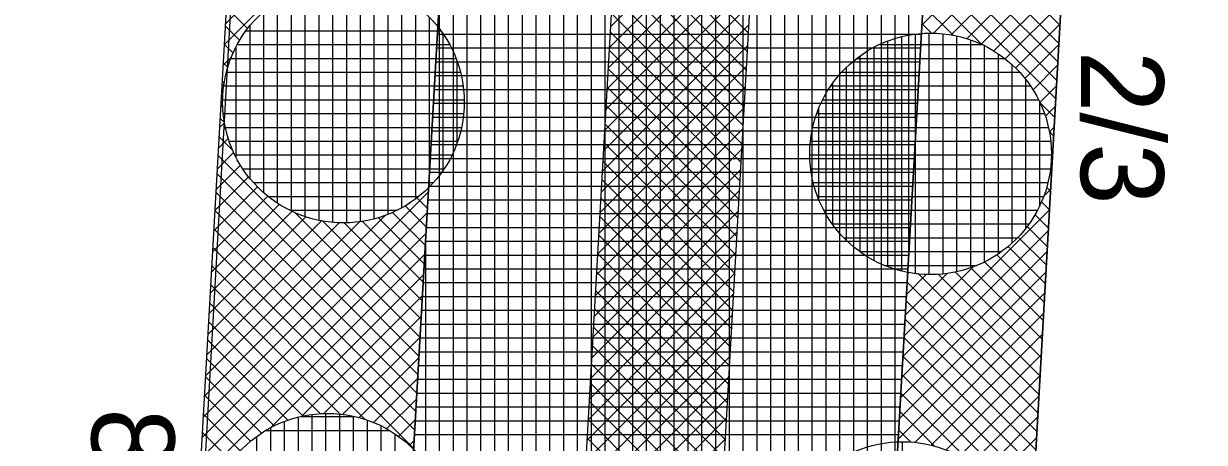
# Model space of a CAD drawing. Extents: x -565346 to -564154, y -1097386 to -1095620.
# Drawn here: x -564301.42 to -564284.31, y -1097175.5 to -1097169.44 of the extents above; entities that cross this region are included whole.
import ezdxf

# ---------------------------------------------------------------- set-up
doc = ezdxf.new("R2010")
doc.units = 0
for name, color, linetype in [('Vrstva 1', 7, 'Continuous'), ('Vrstva 13', 7, 'Continuous'), ('Vrstva 40', 7, 'Continuous'), ('Vrstva 41', 7, 'Continuous'), ('Vrstva 42', 7, 'Continuous'), ('Vrstva 43', 7, 'Continuous'), ('Vrstva 44', 7, 'Continuous')]:
    doc.layers.add(name, color=color, linetype=linetype)

msp = doc.modelspace()

# ---------------------------------------------------------------- linework, layer by layer
at = {"layer": 'Vrstva 1'}
msp.add_line((-564307.09, -1097322.09), (-564296.5, -1097135.53), dxfattribs=at)
at = {"layer": 'Vrstva 13'}
msp.add_line((-564284.61, -1097137.94), (-564287.03, -1097180.53), dxfattribs=at)
at = {"layer": 'Vrstva 41'}
for points in [[(-564307.383, -1097332.191), (-564304.399, -1097332.838), (-564304.096, -1097322.37), (-564303.226, -1097307.04), (-564296.016, -1097180.02), (-564294.347, -1097150.646), (-564297.42, -1097150.37), (-564307.09, -1097322.09)], [(-564297.082, -1097322.329), (-564302.848, -1097333.175), (-564300.817, -1097333.615), (-564295.11, -1097322.88), (-564285.364, -1097151.156), (-564287.358, -1097151.043), (-564289.027, -1097180.417), (-564293.197, -1097253.877), (-564296.237, -1097307.437)]]:
    msp.add_lwpolyline(points, close=True, dxfattribs=at)
at = {"layer": 'Vrstva 42'}
for p, q in [((-564295.23, -1097166.181), (-564298.494, -1097169.446)), ((-564295.247, -1097166.481), (-564298.511, -1097169.745)), ((-564290.789, -1097167.357), (-564292.913, -1097169.481)), ((-564286.283, -1097167.34), (-564288.405, -1097169.461)), ((-564288.297, -1097167.563), (-564286.403, -1097169.457)), ((-564290.806, -1097167.656), (-564292.93, -1097169.781)), ((-564292.811, -1097167.681), (-564290.915, -1097169.577)), ((-564286.3, -1097167.64), (-564288.236, -1097169.576)), ((-564290.823, -1097167.956), (-564292.947, -1097170.08)), ((-564292.826, -1097167.949), (-564290.93, -1097169.845)), ((-564288.312, -1097167.831), (-564286.418, -1097169.725)), ((-564286.317, -1097167.939), (-564287.979, -1097169.601)), ((-564288.327, -1097168.099), (-564286.433, -1097169.992)), ((-564290.84, -1097168.256), (-564292.964, -1097170.38)), ((-564292.841, -1097168.217), (-564290.946, -1097170.112)), ((-564286.334, -1097168.239), (-564287.75, -1097169.655)), ((-564288.342, -1097168.366), (-564286.449, -1097170.26)), ((-564290.857, -1097168.556), (-564292.981, -1097170.68)), ((-564292.856, -1097168.484), (-564290.961, -1097170.38)), ((-564288.357, -1097168.634), (-564286.464, -1097170.528)), ((-564286.351, -1097168.539), (-564287.545, -1097169.733)), ((-564292.872, -1097168.752), (-564290.976, -1097170.648)), ((-564290.874, -1097168.856), (-564292.998, -1097170.98)), ((-564288.373, -1097168.902), (-564287.536, -1097169.738)), ((-564286.368, -1097168.839), (-564287.361, -1097169.832)), ((-564290.891, -1097169.156), (-564293.015, -1097171.28)), ((-564292.887, -1097169.02), (-564290.991, -1097170.915)), ((-564286.385, -1097169.139), (-564287.195, -1097169.949)), ((-564298.48, -1097169.199), (-564298.171, -1097169.509)), ((-564292.902, -1097169.287), (-564291.006, -1097171.183)), ((-564288.388, -1097169.169), (-564287.952, -1097169.606)), ((-564298.495, -1097169.467), (-564298.286, -1097169.677)), ((-564295.417, -1097169.48), (-564295.419, -1097169.482)), ((-564290.908, -1097169.456), (-564293.032, -1097171.58)), ((-564288.403, -1097169.437), (-564288.265, -1097169.574)), ((-564286.402, -1097169.439), (-564287.045, -1097170.082)), ((-564292.917, -1097169.555), (-564291.022, -1097171.451)), ((-564298.51, -1097169.735), (-564298.383, -1097169.862)), ((-564290.925, -1097169.756), (-564293.049, -1097171.88)), ((-564292.933, -1097169.822), (-564291.037, -1097171.718)), ((-564286.419, -1097169.739), (-564286.911, -1097170.23)), ((-564298.406, -1097169.924), (-564298.528, -1097170.045)), ((-564298.526, -1097170.003), (-564298.458, -1097170.07)), ((-564290.942, -1097170.055), (-564293.066, -1097172.18)), ((-564292.948, -1097170.09), (-564291.052, -1097171.986)), ((-564286.436, -1097170.038), (-564286.793, -1097170.395)), ((-564298.512, -1097170.312), (-564298.545, -1097170.345)), ((-564298.541, -1097170.27), (-564298.51, -1097170.301)), ((-564290.959, -1097170.355), (-564293.083, -1097172.479)), ((-564286.453, -1097170.338), (-564286.692, -1097170.578)), ((-564292.963, -1097170.358), (-564291.067, -1097172.253)), ((-564298.532, -1097170.615), (-564298.562, -1097170.645)), ((-564298.556, -1097170.538), (-564298.533, -1097170.561)), ((-564290.976, -1097170.655), (-564293.101, -1097172.779)), ((-564292.978, -1097170.625), (-564291.082, -1097172.521)), ((-564286.688, -1097170.586), (-564286.479, -1097170.795)), ((-564286.47, -1097170.638), (-564286.611, -1097170.779)), ((-564298.571, -1097170.806), (-564298.506, -1097170.87)), ((-564298.506, -1097170.872), (-564298.579, -1097170.944)), ((-564290.993, -1097170.955), (-564293.118, -1097173.079)), ((-564292.993, -1097170.893), (-564291.098, -1097172.789)), ((-564286.556, -1097171.002), (-564286.494, -1097171.063)), ((-564286.487, -1097170.938), (-564286.555, -1097171.006)), ((-564298.452, -1097171.101), (-564298.595, -1097171.244)), ((-564298.586, -1097171.074), (-564298.389, -1097171.271)), ((-564293.009, -1097171.161), (-564291.113, -1097173.056)), ((-564298.373, -1097171.305), (-564298.612, -1097171.544)), ((-564298.601, -1097171.341), (-564295.688, -1097174.254)), ((-564291.01, -1097171.255), (-564293.135, -1097173.379)), ((-564286.504, -1097171.238), (-564286.527, -1097171.261)), ((-564286.524, -1097171.315), (-564286.509, -1097171.331)), ((-564298.274, -1097171.489), (-564298.629, -1097171.843)), ((-564293.024, -1097171.428), (-564291.128, -1097173.324)), ((-564286.521, -1097171.538), (-564286.542, -1097171.559)), ((-564298.158, -1097171.655), (-564298.646, -1097172.143)), ((-564298.616, -1097171.609), (-564295.704, -1097174.522)), ((-564291.028, -1097171.555), (-564293.152, -1097173.679)), ((-564293.039, -1097171.696), (-564291.143, -1097173.592)), ((-564286.545, -1097171.578), (-564286.525, -1097171.598)), ((-564295.553, -1097171.879), (-564298.815, -1097175.14)), ((-564298.025, -1097171.804), (-564298.663, -1097172.443)), ((-564298.631, -1097171.877), (-564295.719, -1097174.789)), ((-564295.568, -1097171.829), (-564295.552, -1097171.845)), ((-564291.045, -1097171.855), (-564293.169, -1097173.979)), ((-564286.538, -1097171.838), (-564286.637, -1097171.937)), ((-564286.595, -1097171.81), (-564286.54, -1097171.866)), ((-564297.711, -1097172.056), (-564298.697, -1097173.042)), ((-564297.876, -1097171.939), (-564298.68, -1097172.743)), ((-564295.719, -1097171.961), (-564295.567, -1097172.113)), ((-564293.054, -1097171.964), (-564291.158, -1097173.859)), ((-564286.669, -1097172.02), (-564286.555, -1097172.134)), ((-564295.57, -1097172.179), (-564298.832, -1097175.44)), ((-564296.166, -1097172.209), (-564298.798, -1097174.841)), ((-564297.528, -1097172.157), (-564298.714, -1097173.342)), ((-564298.646, -1097172.145), (-564295.734, -1097175.057)), ((-564297.481, -1097172.179), (-564295.673, -1097173.986)), ((-564296.072, -1097172.173), (-564295.597, -1097172.648)), ((-564295.887, -1097172.076), (-564295.582, -1097172.381)), ((-564291.062, -1097172.155), (-564293.186, -1097174.279)), ((-564293.069, -1097172.231), (-564291.174, -1097174.127)), ((-564286.555, -1097172.137), (-564288.677, -1097174.259)), ((-564286.764, -1097172.208), (-564286.57, -1097172.401)), ((-564296.546, -1097172.305), (-564298.781, -1097174.541)), ((-564296.841, -1097172.318), (-564298.764, -1097174.241)), ((-564297.097, -1097172.291), (-564298.747, -1097173.942)), ((-564297.326, -1097172.238), (-564298.73, -1097173.642)), ((-564297.084, -1097172.293), (-564295.658, -1097173.719)), ((-564296.771, -1097172.323), (-564295.643, -1097173.451)), ((-564296.511, -1097172.3), (-564295.628, -1097173.183)), ((-564296.28, -1097172.248), (-564295.612, -1097172.916)), ((-564286.877, -1097172.377), (-564286.585, -1097172.669)), ((-564295.588, -1097172.479), (-564298.849, -1097175.74)), ((-564298.661, -1097172.412), (-564295.749, -1097175.325)), ((-564291.079, -1097172.455), (-564293.203, -1097174.579)), ((-564293.085, -1097172.499), (-564291.189, -1097174.395)), ((-564286.572, -1097172.437), (-564288.694, -1097174.559)), ((-564287.008, -1097172.529), (-564286.6, -1097172.937)), ((-564298.676, -1097172.68), (-564295.764, -1097175.592)), ((-564286.589, -1097172.737), (-564288.711, -1097174.859)), ((-564287.154, -1097172.666), (-564286.616, -1097173.204)), ((-564295.605, -1097172.779), (-564298.866, -1097176.04)), ((-564291.096, -1097172.754), (-564293.22, -1097174.879)), ((-564293.1, -1097172.766), (-564291.204, -1097174.662)), ((-564287.496, -1097172.889), (-564286.646, -1097173.739)), ((-564287.316, -1097172.786), (-564286.631, -1097173.472)), ((-564298.691, -1097172.948), (-564296.467, -1097175.172)), ((-564295.622, -1097173.079), (-564297.832, -1097175.289)), ((-564291.113, -1097173.054), (-564293.237, -1097175.178)), ((-564293.115, -1097173.034), (-564291.219, -1097174.93)), ((-564286.606, -1097173.037), (-564288.728, -1097175.159)), ((-564287.661, -1097172.961), (-564288.66, -1097173.96)), ((-564288.039, -1097173.056), (-564288.643, -1097173.66)), ((-564288.334, -1097173.068), (-564288.626, -1097173.36)), ((-564288.59, -1097173.041), (-564288.609, -1097173.06)), ((-564288.463, -1097173.054), (-564286.707, -1097174.81)), ((-564288.166, -1097173.068), (-564286.692, -1097174.542)), ((-564287.915, -1097173.037), (-564286.676, -1097174.275)), ((-564287.695, -1097172.974), (-564286.661, -1097174.007)), ((-564298.707, -1097173.216), (-564296.828, -1097175.094)), ((-564288.616, -1097173.184), (-564286.722, -1097175.078)), ((-564295.639, -1097173.378), (-564297.384, -1097175.124)), ((-564291.13, -1097173.354), (-564293.254, -1097175.478)), ((-564293.13, -1097173.302), (-564291.234, -1097175.197)), ((-564286.623, -1097173.337), (-564288.745, -1097175.459)), ((-564298.722, -1097173.484), (-564297.116, -1097175.09)), ((-564293.145, -1097173.569), (-564291.25, -1097175.465)), ((-564288.631, -1097173.451), (-564286.737, -1097175.345)), ((-564298.737, -1097173.751), (-564297.368, -1097175.12)), ((-564295.656, -1097173.678), (-564297.064, -1097175.087)), ((-564291.147, -1097173.654), (-564293.271, -1097175.778)), ((-564288.646, -1097173.719), (-564286.752, -1097175.613)), ((-564286.64, -1097173.637), (-564288.507, -1097175.504)), ((-564293.161, -1097173.837), (-564291.265, -1097175.733)), ((-564286.657, -1097173.937), (-564288.267, -1097175.546)), ((-564298.752, -1097174.019), (-564297.588, -1097175.183)), ((-564295.673, -1097173.978), (-564296.794, -1097175.1)), ((-564291.164, -1097173.954), (-564293.288, -1097176.078)), ((-564293.176, -1097174.105), (-564291.28, -1097176)), ((-564288.662, -1097173.987), (-564286.768, -1097175.881)), ((-564298.767, -1097174.287), (-564297.787, -1097175.266)), ((-564295.69, -1097174.278), (-564296.559, -1097175.147)), ((-564291.181, -1097174.254), (-564293.305, -1097176.378)), ((-564288.677, -1097174.254), (-564286.783, -1097176.148)), ((-564286.674, -1097174.236), (-564288.052, -1097175.614)), ((-564293.191, -1097174.372), (-564291.295, -1097176.268)), ((-564298.782, -1097174.555), (-564297.968, -1097175.369)), ((-564295.707, -1097174.578), (-564296.347, -1097175.218)), ((-564291.198, -1097174.554), (-564293.322, -1097176.678)), ((-564288.692, -1097174.522), (-564286.798, -1097176.416)), ((-564286.691, -1097174.536), (-564287.858, -1097175.703)), ((-564293.206, -1097174.64), (-564291.311, -1097176.536)), ((-564288.707, -1097174.79), (-564287.694, -1097175.802)), ((-564298.797, -1097174.822), (-564298.13, -1097175.489)), ((-564295.724, -1097174.878), (-564296.156, -1097175.31)), ((-564291.215, -1097174.854), (-564293.339, -1097176.978)), ((-564293.221, -1097174.908), (-564291.326, -1097176.803)), ((-564286.708, -1097174.836), (-564287.682, -1097175.81)), ((-564298.812, -1097175.09), (-564298.277, -1097175.626)), ((-564288.722, -1097175.057), (-564288.221, -1097175.559)), ((-564286.725, -1097175.136), (-564287.524, -1097175.935)), ((-564295.741, -1097175.178), (-564295.983, -1097175.42)), ((-564291.232, -1097175.153), (-564293.356, -1097177.278)), ((-564293.237, -1097175.175), (-564291.341, -1097177.071)), ((-564298.827, -1097175.358), (-564298.408, -1097175.778)), ((-564295.758, -1097175.478), (-564295.829, -1097175.548)), ((-564291.249, -1097175.453), (-564293.373, -1097177.577)), ((-564293.252, -1097175.443), (-564291.356, -1097177.339)), ((-564288.738, -1097175.325), (-564288.562, -1097175.501)), ((-564286.742, -1097175.436), (-564287.382, -1097176.076))]:
    msp.add_line(p, q, dxfattribs=at)
msp.add_lwpolyline([(-564300.922, -1097310.531), (-564298.925, -1097310.644), (-564291.523, -1097180.275), (-564289.854, -1097150.901), (-564291.851, -1097150.788), (-564293.52, -1097180.162), (-564300.73, -1097307.182)], close=True, dxfattribs=at)
at = {"layer": 'Vrstva 43'}
for p, q in [((-564288.59, -1097172.726), (-564288.59, -1097040.388)), ((-564288.79, -1097176.246), (-564288.79, -1097043.908)), ((-564288.99, -1097179.766), (-564288.99, -1097047.427)), ((-564289.19, -1097183.288), (-564289.19, -1097050.947)), ((-564289.39, -1097186.812), (-564289.39, -1097054.467)), ((-564289.59, -1097190.335), (-564289.59, -1097057.987)), ((-564289.79, -1097193.858), (-564289.79, -1097061.507)), ((-564289.99, -1097197.382), (-564289.99, -1097065.027)), ((-564290.19, -1097200.905), (-564290.19, -1097068.547)), ((-564290.39, -1097204.428), (-564290.39, -1097072.067)), ((-564290.59, -1097207.951), (-564290.59, -1097075.587)), ((-564290.79, -1097211.475), (-564290.79, -1097079.106)), ((-564290.99, -1097214.998), (-564290.99, -1097082.626)), ((-564291.19, -1097218.521), (-564291.19, -1097086.146)), ((-564291.39, -1097222.044), (-564291.39, -1097089.666)), ((-564291.59, -1097225.568), (-564291.59, -1097093.186)), ((-564291.79, -1097229.091), (-564291.79, -1097096.706)), ((-564291.99, -1097232.614), (-564291.99, -1097100.226)), ((-564292.19, -1097236.137), (-564292.19, -1097103.746)), ((-564292.39, -1097239.661), (-564292.39, -1097107.266)), ((-564292.59, -1097243.184), (-564292.59, -1097110.785)), ((-564292.79, -1097246.707), (-564292.79, -1097114.305)), ((-564292.99, -1097250.23), (-564292.99, -1097117.825)), ((-564293.19, -1097253.754), (-564293.19, -1097121.345)), ((-564293.39, -1097257.278), (-564293.39, -1097124.865)), ((-564293.59, -1097260.802), (-564293.59, -1097128.385)), ((-564293.79, -1097264.325), (-564293.79, -1097131.905)), ((-564293.99, -1097267.849), (-564293.99, -1097135.425)), ((-564294.19, -1097271.373), (-564294.19, -1097138.944)), ((-564294.39, -1097274.897), (-564294.39, -1097151.403)), ((-564294.59, -1097278.421), (-564294.59, -1097154.926)), ((-564294.79, -1097281.945), (-564294.79, -1097158.449)), ((-564294.99, -1097285.469), (-564294.99, -1097161.972)), ((-564295.19, -1097288.993), (-564295.19, -1097165.495)), ((-564295.39, -1097292.517), (-564295.39, -1097169.017)), ((-564295.423, -1097169.59), (-564288.412, -1097169.59)), ((-564295.434, -1097169.79), (-564288.423, -1097169.79)), ((-564295.445, -1097169.99), (-564288.435, -1097169.99)), ((-564295.457, -1097170.19), (-564288.446, -1097170.19)), ((-564295.468, -1097170.39), (-564288.457, -1097170.39)), ((-564295.479, -1097170.59), (-564288.469, -1097170.59)), ((-564295.491, -1097170.79), (-564288.48, -1097170.79)), ((-564295.502, -1097170.99), (-564288.491, -1097170.99)), ((-564295.513, -1097171.19), (-564288.503, -1097171.19)), ((-564295.525, -1097171.39), (-564288.514, -1097171.39)), ((-564295.536, -1097171.59), (-564288.525, -1097171.59)), ((-564295.547, -1097171.79), (-564288.537, -1097171.79)), ((-564295.559, -1097171.99), (-564288.548, -1097171.99)), ((-564295.57, -1097172.19), (-564288.56, -1097172.19)), ((-564295.581, -1097172.39), (-564288.571, -1097172.39)), ((-564295.59, -1097296.041), (-564295.59, -1097172.54)), ((-564295.593, -1097172.59), (-564288.582, -1097172.59)), ((-564295.604, -1097172.79), (-564288.594, -1097172.79)), ((-564295.616, -1097172.99), (-564288.605, -1097172.99)), ((-564295.627, -1097173.19), (-564288.616, -1097173.19)), ((-564295.638, -1097173.39), (-564288.628, -1097173.39)), ((-564295.65, -1097173.59), (-564288.639, -1097173.59)), ((-564295.661, -1097173.79), (-564288.65, -1097173.79)), ((-564295.672, -1097173.99), (-564288.662, -1097173.99)), ((-564295.684, -1097174.19), (-564288.673, -1097174.19)), ((-564295.695, -1097174.39), (-564288.685, -1097174.39)), ((-564295.706, -1097174.59), (-564288.696, -1097174.59)), ((-564295.718, -1097174.79), (-564288.707, -1097174.79)), ((-564295.729, -1097174.99), (-564288.719, -1097174.99)), ((-564295.74, -1097175.19), (-564288.73, -1097175.19)), ((-564295.752, -1097175.39), (-564288.741, -1097175.39))]:
    msp.add_line(p, q, dxfattribs=at)
msp.add_lwpolyline([(-564283.37, -1096906.18), (-564284.87, -1096930.83), (-564282.373, -1096930.972), (-564294.286, -1097140.634), (-564296.782, -1097140.492), (-564297.42, -1097150.37), (-564294.347, -1097150.646), (-564303.226, -1097307.04), (-564304.096, -1097322.37), (-564304.399, -1097332.838), (-564302.848, -1097333.175), (-564297.082, -1097322.329), (-564293.197, -1097253.877), (-564289.027, -1097180.417), (-564287.358, -1097151.043), (-564285.364, -1097151.156), (-564284.798, -1097141.172), (-564286.791, -1097141.059), (-564274.888, -1096931.397), (-564272.899, -1096931.51), (-564271.475, -1096906.55)], dxfattribs=at)
at = {"layer": 'Vrstva 44'}
for p, q in [((-564297.34, -1097168.917), (-564297.34, -1097172.231)), ((-564297.14, -1097168.863), (-564297.14, -1097172.286)), ((-564296.94, -1097168.832), (-564296.94, -1097172.315)), ((-564296.74, -1097168.825), (-564296.74, -1097172.322)), ((-564296.54, -1097168.843), (-564296.54, -1097172.306)), ((-564296.34, -1097168.883), (-564296.34, -1097172.267)), ((-564296.14, -1097168.948), (-564296.14, -1097172.201)), ((-564297.74, -1097169.111), (-564297.74, -1097172.038)), ((-564297.54, -1097168.998), (-564297.54, -1097172.15)), ((-564295.94, -1097169.041), (-564295.94, -1097172.106)), ((-564297.94, -1097169.264), (-564297.94, -1097171.884)), ((-564295.74, -1097169.171), (-564295.74, -1097171.98)), ((-564298.14, -1097169.473), (-564298.14, -1097171.676)), ((-564295.54, -1097169.343), (-564295.54, -1097171.804)), ((-564298.194, -1097169.54), (-564295.373, -1097169.54)), ((-564295.34, -1097169.583), (-564295.34, -1097171.562)), ((-564288.7, -1097169.628), (-564288.7, -1097173.021)), ((-564288.5, -1097169.59), (-564288.5, -1097173.059)), ((-564288.3, -1097169.576), (-564288.3, -1097173.073)), ((-564288.1, -1097169.584), (-564288.1, -1097173.063)), ((-564287.9, -1097169.616), (-564287.9, -1097173.031)), ((-564298.34, -1097169.781), (-564298.34, -1097171.367)), ((-564298.319, -1097169.74), (-564295.245, -1097169.74)), ((-564289.1, -1097169.782), (-564289.1, -1097172.867)), ((-564289.016, -1097169.74), (-564287.536, -1097169.74)), ((-564288.9, -1097169.689), (-564288.9, -1097172.958)), ((-564287.7, -1097169.673), (-564287.7, -1097172.975)), ((-564287.5, -1097169.757), (-564287.5, -1097172.892)), ((-564298.412, -1097169.94), (-564295.153, -1097169.94)), ((-564295.14, -1097169.975), (-564295.14, -1097171.178)), ((-564289.346, -1097169.94), (-564287.207, -1097169.94)), ((-564289.3, -1097169.907), (-564289.3, -1097172.74)), ((-564287.3, -1097169.872), (-564287.3, -1097172.774)), ((-564298.477, -1097170.14), (-564295.089, -1097170.14)), ((-564289.563, -1097170.14), (-564286.99, -1097170.14)), ((-564289.5, -1097170.076), (-564289.5, -1097172.573)), ((-564287.1, -1097170.03), (-564287.1, -1097172.62)), ((-564298.515, -1097170.34), (-564295.049, -1097170.34)), ((-564289.721, -1097170.34), (-564286.829, -1097170.34)), ((-564289.7, -1097170.308), (-564289.7, -1097172.34)), ((-564286.9, -1097170.245), (-564286.9, -1097172.403)), ((-564298.53, -1097170.54), (-564295.033, -1097170.54)), ((-564289.9, -1097170.678), (-564289.9, -1097171.97)), ((-564289.838, -1097170.54), (-564286.713, -1097170.54)), ((-564286.7, -1097170.567), (-564286.7, -1097172.085)), ((-564298.522, -1097170.74), (-564295.042, -1097170.74)), ((-564289.925, -1097170.74), (-564286.628, -1097170.74)), ((-564298.492, -1097170.94), (-564295.073, -1097170.94)), ((-564289.982, -1097170.94), (-564286.569, -1097170.94)), ((-564298.438, -1097171.14), (-564295.128, -1097171.14)), ((-564290.014, -1097171.14), (-564286.537, -1097171.14)), ((-564298.354, -1097171.34), (-564295.209, -1097171.34)), ((-564290.024, -1097171.34), (-564286.528, -1097171.34)), ((-564298.24, -1097171.54), (-564295.325, -1097171.54)), ((-564290.011, -1097171.54), (-564286.541, -1097171.54)), ((-564298.086, -1097171.74), (-564295.478, -1097171.74)), ((-564289.975, -1097171.74), (-564286.577, -1097171.74)), ((-564297.876, -1097171.94), (-564295.691, -1097171.94)), ((-564289.912, -1097171.94), (-564286.638, -1097171.94)), ((-564297.561, -1097172.14), (-564296.003, -1097172.14)), ((-564289.822, -1097172.14), (-564286.73, -1097172.14)), ((-564289.7, -1097172.34), (-564286.853, -1097172.34)), ((-564289.532, -1097172.54), (-564287.02, -1097172.54)), ((-564289.301, -1097172.74), (-564287.249, -1097172.74)), ((-564288.945, -1097172.94), (-564287.609, -1097172.94)), ((-564297.44, -1097175.139), (-564297.44, -1097178.53)), ((-564297.401, -1097175.13), (-564296.619, -1097175.13)), ((-564297.24, -1097175.101), (-564297.24, -1097178.569)), ((-564297.04, -1097175.086), (-564297.04, -1097178.583)), ((-564296.84, -1097175.093), (-564296.84, -1097178.574)), ((-564296.64, -1097175.125), (-564296.64, -1097178.542)), ((-564297.84, -1097175.295), (-564297.84, -1097178.374)), ((-564297.64, -1097175.201), (-564297.64, -1097178.466)), ((-564296.44, -1097175.182), (-564296.44, -1097178.487)), ((-564296.24, -1097175.265), (-564296.24, -1097178.404)), ((-564298.04, -1097175.42), (-564298.04, -1097178.248)), ((-564297.903, -1097175.33), (-564296.121, -1097175.33)), ((-564296.04, -1097175.379), (-564296.04, -1097178.287)), ((-564288.69, -1097175.495), (-564288.69, -1097178.992))]:
    msp.add_line(p, q, dxfattribs=at)
for centre in [(-564296.782, -1097170.574), (-564288.276, -1097171.324), (-564297.011, -1097176.834), (-564288.685, -1097177.244)]:
    msp.add_circle(centre, 1.75, dxfattribs=at)

# ---------------------------------------------------------------- texts
at = {"layer": 'Vrstva 40'}
for s, p in [('2/3', (-564286.1, -1097169.83)), ('8/3', (-564300.43, -1097175.01))]:
    msp.add_text(s, height=1.2, rotation=270, dxfattribs=at).set_placement(p)

doc.saveas('drawing.dxf')
